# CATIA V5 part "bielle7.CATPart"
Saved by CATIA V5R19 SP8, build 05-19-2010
Part number: Pièce7
Bounding box of the stored display mesh (mm): x -83.973 to -15.992, y 32.952 to 100.728, z -204.62 to 310
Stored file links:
  G:\EU_thinkMotion\CFAO_2010\SIL_groupe1\SIL_groupe1\A reprendre\lalpha\lalpha\Alpha.mécanisme\bielle7.CATPart
  G:\EU_thinkMotion\CFAO_2010\SIL_groupe1\SIL_groupe1\A reprendre\lalpha\lalpha\Alpha.mécanisme\bati.CATPart
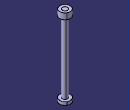
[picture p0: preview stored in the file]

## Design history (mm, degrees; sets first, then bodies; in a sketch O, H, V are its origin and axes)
Body1 (main body)
  Line1: stored without definition
  Sketch1, origin (0, 0, 315.2607), H (1, 0, 0), V (0, 1, 0), geometry linked from another document
  Plane1: type Normal, Curve Line1, RefPoint Sketch1
  Sketch2, origin (0, 0, 315.2607), H (1, 0, 0), V (0, 1, 0), geometry linked from another document
  Plane2: type Angle, RefPlane Plane1, Direction Sketch2, Angle 90
  Sketch3 on Plane2, origin (-49.9827, 0, 0), H (0, 1, 0), V (0, 0, 1)
    line L1 (66.8398, 310) -> (83.5299, 310)
    line L2 (83.5299, 271.634) -> (83.5299, -183.392)
    line L3 (83.5299, -204.6199) -> (66.8398, -204.6199)
    line L4 (66.8398, -204.6199) -> (66.8398, 310)
    line L5 (83.5299, 310) -> (100.1333, 310)
    line L6 (100.1333, 310) -> (100.1333, 271.634)
    line L7 (100.1333, 271.634) -> (83.5299, 271.634)
    line L8 (83.5299, -204.6199) -> (100.8398, -204.6199)
    line L9 (100.8398, -204.6199) -> (100.8398, -183.392)
    line L10 (100.8398, -183.392) -> (83.5299, -183.392)
    horizontal: L1 H, L3 H, L5 H, L7 H, L8 H, L10 H
    vertical: L2 V, L4 V, L6 V, L9 V
  Shaft1: profile Sketch3, axis Sketch3.L4, angle 360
